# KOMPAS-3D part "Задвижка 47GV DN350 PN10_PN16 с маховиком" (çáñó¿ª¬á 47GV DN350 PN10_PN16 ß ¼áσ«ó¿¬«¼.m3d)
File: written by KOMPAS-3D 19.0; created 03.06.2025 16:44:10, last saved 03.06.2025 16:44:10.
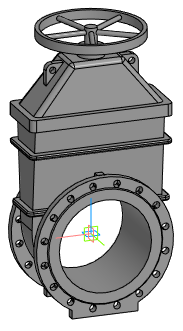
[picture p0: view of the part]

Document properties: Автор: Евгений; Полное имя файла: E:\Dendor Работа Сачек\3D для проекитирвщиков\2.1 Тип 47GV, 47GV.Z Задвижка клиновая фланцевая с обрезиненным клином\stp_Тип 47GV. Задвижка DN40-DN350 с маховиком\Задвижка 47GV DN350 PN10_PN16 с маховиком.m3d

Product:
- Part/product: Задвижка 47GV DN350 PN10_PN16 с маховиком

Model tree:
1. Операция без истории:1  (labels: Задвижка 47GV DN350 PN10_PN16 с маховиком)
